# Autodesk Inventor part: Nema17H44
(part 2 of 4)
sketch "Эскиз49"
  geometry: L1 (-4, 0)-(-4, 283.577) reference; L2 (0, 283.577)-(0, 0) reference; L3 (0, 0)-(-4, 0) reference; L4 (-4, 283.577)-(0, 283.577) reference; L5 (0, 0)-(60, 0); L6 (60, 0)-(60, 283.577); L7 (60, 283.577)-(0, 283.577); L8 (0, 283.577)-(0, 0); L9 (-4, 25)-(0, 25); L10 (0, 25)-(0, 55); L11 (0, 55)-(-4, 55); L12 (-4, 55)-(-4, 25); L13 (0, 122.859)-(-4, 122.859); L14 (0, 92.859)-(0, 122.859); L15 (-4, 122.859)-(-4, 92.859); L16 (-4, 92.859)-(0, 92.859); L17 (0, 190.718)-(-4, 190.718); L18 (0, 160.718)-(0, 190.718); L19 (-4, 190.718)-(-4, 160.718); L20 (-4, 160.718)-(0, 160.718); L21 (0, 258.577)-(-4, 258.577); L22 (0, 228.577)-(0, 258.577); L23 (-4, 258.577)-(-4, 228.577); L24 (-4, 228.577)-(0, 228.577); L25 (0, 260)-(0, 283.577) reference; L26 (26.106, 260.239)-(0, 260) reference; L27 (0, 283.577)-(26.106, 283.338) reference; C1 r 12 at (26, 24.788) reference; C2 r 4 at (26, 271.788) reference; C3 r 4 at (26, 24.788); C4 r 4 at (26, 271.788); C5 r 2.25 at (10.45, 40.338) reference; C6 r 2.25 at (41.55, 40.338) reference; C7 r 2.25 at (10.45, 9.238) reference; C8 r 2.25 at (41.55, 9.238) reference; C9 r 7.35 at (26, 271.788) reference; C10 r 1.5 at (10.45, 40.338) reference; C11 r 1.5 at (41.55, 40.338) reference; C12 r 1.5 at (41.55, 9.238) reference; C13 r 1.5 at (10.45, 9.238) reference; A1 r 11.55 centre (26, 271.788) between (26.106, 260.239) and (26.106, 283.338) reference; 17 further points
  constraints: 40 end point, 4 parallel, 2 centre point, 2 coincident, 2 horizontal, 2 perpendicular, 2 point on line, 1 vertical, 24 other
  dimensions: "d382" = 60 distance of L2.end L5.end; "d383" = 8 diameter of C3; "d384" = 8 diameter of C4; "d385" = 30 distance between parallel lines of L9 L11; "d386" = 25 distance between parallel lines of L3 L9; "d389" = 67.85896 distance of L10.end L13.start (derived); "d394" = 25 distance from line of L21 L1.end
extrude "Выдавливание34" new body sketch "Эскиз49" distance "d395" = 4; taper "d396" = 0 deg
sketch "Эскиз50"
  geometry: C1 r 1.5 at (-16, 247) reference; C2 r 2 at (-16, 247); 1 further point
  constraints: 1 centre point, 1 coincident
  dimensions: "d399" = 4 diameter of C2
extrude "Выдавливание35" cut sketch "Эскиз50" distance "d400" = 4; taper "d401" = 0 deg
sketch "Эскиз51"
  geometry: C1 r 2 at (-16, 247); C2 r 4 at (-16, 247); A1 r 2 centre (-16, 247) between (-15.929, 245.001) and (-15.929, 248.999) reference; 3 further points
  constraints: 2 centre point, 2 coincident
  dimensions: "d402" = 4 diameter of C1; "d403" = 8 diameter of C2
extrude "Выдавливание36" join sketch "Эскиз51" distance "d404" = 1.5; taper "d405" = 0 deg
fillet "Сопряжение23" dims "d406" = 1
chamfer "Фаска24" distance "d407" = 0.5; stored, may be unused: second distance "d408" = 8, angle "d409" = 45 deg
fillet "Сопряжение24" dims "d410" = 1
feature "Комбинировать1"
feature "Толщина1" dims "d411" = 0.1, "d412" = 0.1
feature "Толщина2" dims "d413" = 0.1, "d414" = 0.1
feature "Толщина3" dims "d415" = 0.1, "d416" = 0.1
feature "Толщина4" dims "d417" = 0.1, "d418" = 0.1
sketch "Эскиз56"
  geometry: L1 (17.172, 21)-(-17.172, 21); L2 (-22, 16.172)-(-22, -16.172); L3 (-21.414, -17.586)-(-18.586, -20.414); L4 (-17.172, -21)-(17.172, -21); L5 (22, -16.172)-(22, 16.172); L6 (21.414, 17.586)-(18.586, 20.414); L7 (18.586, -20.414)-(21.414, -17.586); L8 (-18.586, 20.414)-(-21.414, 17.586); C1 r 1.9 at (-15.25, -15.25); C2 r 12 at (0, 0); C3 r 1.9 at (15.25, -15.25); C4 r 1.9 at (-15.25, 15.25); C5 r 1.9 at (15.25, 15.25); C6 r 4 at (0, 0) reference; A1 r 2 centre (-20, -16.172) between (-22, -16.172) and (-21.414, -17.586); A2 r 2 centre (-17.172, -19) between (-18.586, -20.414) and (-17.172, -21); A3 r 2 centre (20, -16.172) between (21.414, -17.586) and (22, -16.172); A4 r 2 centre (17.172, -19) between (17.172, -21) and (18.586, -20.414); A5 r 2 centre (17.172, 19) between (18.586, 20.414) and (17.172, 21); A6 r 2 centre (20, 16.172) between (22, 16.172) and (21.414, 17.586); A7 r 2 centre (-17.172, 19) between (-17.172, 21) and (-18.586, 20.414); A8 r 2 centre (-20, 16.172) between (-21.414, 17.586) and (-22, 16.172); 4 further points
  constraints: 16 end point, 16 point on circle, 13 centre point, 2 midpoint, 1 horizontal alignment, 1 vertical alignment
extrude "Выдавливание41" new body sketch "Эскиз56" distance "d440" = 40; taper "d441" = 0 deg
sketch "Эскиз57"
  geometry: L1 (-42.586, 38.857)-(-45.414, 36.028); L2 (-46, 34.614)-(-46, 2.271); L3 (-6.828, 39.443)-(-41.172, 39.443); L4 (-45.414, 0.857)-(-42.586, -1.972); L5 (-2, 2.271)-(-2, 34.614); L6 (-41.172, -2.557)-(-6.828, -2.557); L7 (-5.414, -1.972)-(-2.586, 0.857); L8 (-2.586, 36.028)-(-5.414, 38.857); L9 (-42.586, 266.553)-(-45.414, 263.724); L10 (-46, 262.31)-(-46, 229.967); L11 (-6.828, 267.139)-(-41.172, 267.139); L12 (-45.414, 228.553)-(-42.586, 225.724); L13 (-2, 229.967)-(-2, 262.31); L14 (-41.172, 225.139)-(-6.828, 225.139); L15 (-5.414, 225.724)-(-2.586, 228.553); L16 (-2.586, 263.724)-(-5.414, 266.553); C1 r 1.9 at (-39.25, 33.693); C2 r 1.9 at (-39.25, 3.193); C3 r 1.9 at (-8.75, 33.693); C4 r 12 at (-24, 18.443); C5 r 1.9 at (-8.75, 3.193); C6 r 1.9 at (-39.25, 261.389); C7 r 1.9 at (-39.25, 230.889); C8 r 1.9 at (-8.75, 261.389); C9 r 12 at (-24, 246.139); C10 r 1.9 at (-8.75, 230.889); A1 r 2 centre (-44, 34.614) between (-45.414, 36.028) and (-46, 34.614); A2 r 2 centre (-41.172, 37.443) between (-41.172, 39.443) and (-42.586, 38.857); A3 r 2 centre (-44, 2.271) between (-46, 2.271) and (-45.414, 0.857); A4 r 2 centre (-41.172, -0.557) between (-42.586, -1.972) and (-41.172, -2.557); A5 r 2 centre (-6.828, -0.557) between (-6.828, -2.557) and (-5.414, -1.972); A6 r 2 centre (-4, 2.271) between (-2.586, 0.857) and (-2, 2.271); A7 r 2 centre (-6.828, 37.443) between (-5.414, 38.857) and (-6.828, 39.443); A8 r 2 centre (-4, 34.614) between (-2, 34.614) and (-2.586, 36.028); A9 r 2 centre (-44, 262.31) between (-45.414, 263.724) and (-46, 262.31); A10 r 2 centre (-41.172, 265.139) between (-41.172, 267.139) and (-42.586, 266.553); A11 r 2 centre (-44, 229.967) between (-46, 229.967) and (-45.414, 228.553); A12 r 2 centre (-41.172, 227.139) between (-42.586, 225.724) and (-41.172, 225.139); A13 r 2 centre (-6.828, 227.139) between (-6.828, 225.139) and (-5.414, 225.724); A14 r 2 centre (-4, 229.967) between (-2.586, 228.553) and (-2, 229.967); A15 r 2 centre (-6.828, 265.139) between (-5.414, 266.553) and (-6.828, 267.139); A16 r 2 centre (-4, 262.31) between (-2, 262.31) and (-2.586, 263.724); A17 r 13 centre (-24, 246.139) between (-20.15, 233.722) and (-27.85, 233.722) reference; A18 r 13 centre (-24, 18.443) between (-27.85, 30.859) and (-20.15, 30.859) reference; 3 further points
  constraints: 32 end point, 32 point on circle, 26 centre point
extrude "Выдавливание42" join sketch "Эскиз57" distance "d442" = 40; taper "d443" = 0 deg
sketch "Эскиз58"
  geometry: C1 r 3.65 at (15.55, -15.55) reference; C2 r 1.65 at (15.55, -15.55) reference; C3 r 1.65 at (-15.55, -15.55) reference; C4 r 2 at (-15.55, -15.55); C5 r 2 at (15.55, -15.55); C6 r 3.65 at (15.55, -212.146) reference; C7 r 3.65 at (-15.55, -212.146) reference; C8 r 2 at (15.55, -212.146); C9 r 2 at (-15.55, -212.146); 1 further point
  constraints: 4 centre point, 4 coincident, 3 equal radius
  dimensions: "d444" = 4 diameter of C4
extrude "Выдавливание43" cut sketch "Эскиз58" distance "d446" = 5; taper "d447" = 0 deg
chamfer "Фаска25" distance "d448" = 1; stored, may be unused: second distance "d449" = 2, angle "d450" = 45 deg
node "РабПлоскость9"
sketch "Эскиз73"
  geometry: L1 (321, 97.659)-(321, 122.613); L2 (325.8, 34.5)-(325.8, 41.5); L3 (321, 41.5)-(321, 34.5); L4 (322.5, 34.3)-(322.5, 29.5); L5 (322.5, 29.5)-(329, 29.5); L6 (329, 29.5)-(329, 46.5); L7 (329, 46.5)-(322.5, 46.5); L8 (322.5, 46.5)-(322.5, 41.7); L9 (322.5, 41.7)-(326, 41.7); L10 (326, 41.7)-(326, 34.3); L11 (326, 34.3)-(322.5, 34.3); L12 (321, -2.5)-(321, 57.5) reference; L13 (332, 29.5)-(340, 29.5) reference; L14 (325.8, 38)-(323.934, 38); L15 (321, 34.5)-(324.333, 34.5); L16 (325.333, 34.5)-(325.8, 34.5); L17 (325.8, 41.5)-(325.333, 41.5); L18 (324.333, 41.5)-(321, 41.5); A1 r 0.5 centre (324.833, 34.5) between (325.333, 34.5) and (324.333, 34.5); A2 r 0.5 centre (324.833, 41.5) between (324.333, 41.5) and (325.333, 41.5); 2 further points
  constraints: 32 end point, 6 parallel, 5 horizontal, 4 perpendicular, 4 point on circle, 4 vertical, 3 symmetric about line, 2 centre point, 2 collinear, 2 equal length, 2 horizontal alignment, 2 midpoint, 1 point on line, 1 other
  dimensions: "d549" = 4.8 distance of L2.end L3.start; "d550" = 7 distance of L2.start L2.end; "d552" = 0.2 distance between parallel lines of L2 L10; "d553" = 6.5 distance of L4.end L5.end; "d554" = 1.5 distance between parallel lines of L1 L4; "d555" = 17 distance of L5.end L6.end; "d560" = 1.16667 distance from line of L10 A1.centre (derived); "d561" = 2.33333 distance from line of L4 A1.centre (derived); "d562" = 1 diameter of A1; "d563" = 4.8 distance between parallel lines of L3 L2; "d564" = 0.2 distance between parallel lines of L18 L9 (derived)
extrude "Выдавливание55" new body sketch "Эскиз73" stored distance "d556" = 22.5; taper "d558" = 0 deg; dims "d557" = 105, "d559" = 0
node "РабПлоскость12"
sketch "Эскиз74"
  geometry: L1 (325.8, -41.5)-(325.8, -34.5) reference; L2 (325.8, -34.5)-(325.333, -34.5) reference; L3 (324.333, -34.5)-(321, -34.5) reference; L4 (321, -34.5)-(321, -41.5) reference; L5 (321, -41.5)-(324.333, -41.5) reference; L6 (325.333, -41.5)-(325.8, -41.5) reference; A1 r 0.5 centre (324.833, -34.5) between (324.333, -34.5) and (325.333, -34.5) reference; A2 r 0.5 centre (324.833, -41.5) between (325.333, -41.5) and (324.333, -41.5) reference; 1 further point
extrude "Выдавливание56" new body sketch "Эскиз74" distance "d565" = 98; taper "d567" = 0 deg; dims "d566" = 122, "d568" = 0
sketch "Эскиз75"
  geometry: L1 (325.8, -41.5)-(325.8, -34.5) reference; L2 (325.8, -34.5)-(325.333, -34.5) reference; L3 (324.333, -34.5)-(321, -34.5) reference; L4 (321, -34.5)-(321, -41.5) reference; L5 (321, -41.5)-(324.333, -41.5) reference; L6 (325.333, -41.5)-(325.8, -41.5) reference; A1 r 0.5 centre (324.833, -34.5) between (324.333, -34.5) and (325.333, -34.5) reference; A2 r 0.5 centre (324.833, -41.5) between (325.333, -41.5) and (324.333, -41.5) reference; 1 further point
extrude "Выдавливание57" cut sketch "Эскиз75" distance "d569" = 95; taper "d570" = 0 deg
sketch "Эскиз76"
  geometry: L1 (6, -0.013)-(6.55, 246.985); L2 (8, 247)-(8, 0); L3 (0, 0)-(0, 247); L4 (-6, -0.013)-(-6.55, 246.985); L5 (-8, 247)-(-8, 0); C1 r 3 at (0, 0) reference; C2 r 3 at (0, 247) reference; A1 r 6.55 centre (0, 247) between (6.55, 246.985) and (-6.55, 246.985); A2 r 8 centre (0, 247) between (8, 247) and (-8, 247); A3 r 6 centre (0, 0) between (-6, -0.013) and (6, -0.013); A4 r 8 centre (0, 0) between (-8, 0) and (8, 0); 8 further points
  constraints: 10 end point, 8 point on circle, 8 tangent, 4 centre point, 4 symmetric about line, 3 vertical, 1 horizontal alignment, 9 other
extrude "Выдавливание58" new body sketch "Эскиз76" distance "d572" = 6; taper "d573" = 0 deg
sketch "Эскиз78"
  geometry: L1 (-14.5, 7.25)-(-2.5, 7.25); L2 (-2.5, 7.25)-(-2.5, 15.25); L3 (-2.5, 15.25)-(-14.5, 15.25); L4 (-14.5, 15.25)-(-14.5, 7.25); L5 (0, 0)-(0, 22.5) reference; L6 (-17, 22.5)-(0, 22.5) reference; L7 (-17, 0)-(-17, 22.5) reference; L8 (0, 0)-(-17, 0) reference; C1 r 1 at (-14.5, 7.25); C2 r 1 at (-14.5, 15.25); C3 r 1 at (-2.5, 7.25); C4 r 1 at (-2.5, 15.25); 8 further points
  constraints: 8 end point, 4 centre point, 4 coincident, 4 midpoint, 2 horizontal, 2 parallel, 1 horizontal alignment, 1 perpendicular, 1 vertical, 1 vertical alignment, 9 other
  dimensions: "d575" = 12 distance of L3.end L2.end; "d576" = 8 distance of L2.end L1.end; "d579" = 8 distance of L1.start point (-14.5, 15.25) (derived); "d582" = 12 distance of L1.start point (-2.5, 7.25) (derived); "d585" = 2 diameter of C1
extrude "Выдавливание59" cut sketch "Эскиз78" distance "d586" = 5; taper "d587" = 0 deg
sketch "Эскиз79"
  geometry: L1 (0, 0)-(0, 22.5) reference; L2 (-17, 22.5)-(0, 22.5) reference; L3 (-17, 0)-(-17, 22.5) reference; L4 (0, 0)-(-17, 0) reference; C1 r 1 at (-14.5, 15.25) reference; C2 r 1 at (-14.5, 7.25) reference; C3 r 1 at (-2.5, 15.25) reference; C4 r 1 at (-2.5, 7.25) reference; 1 further point
extrude "Выдавливание60" new body sketch "Эскиз79" distance "d588" = 3; taper "d589" = 0 deg
sketch "Эскиз80"
  geometry: L1 (-17, 22.5)-(-17, 0) reference; L2 (-17, 20.25)-(63, 20.25); L3 (63, 20.25)-(63, 2.25); L4 (63, 2.25)-(-17, 2.25); L5 (-17, 2.25)-(-17, 20.25); C1 r 1 at (-2.5, 15.25) reference; C2 r 1 at (-2.5, 7.25) reference; C3 r 1 at (-14.5, 15.25) reference; C4 r 1 at (-14.5, 7.25) reference; 4 further points
  constraints: 8 end point, 2 midpoint, 2 parallel, 1 horizontal, 1 horizontal alignment, 1 perpendicular, 1 point on line
  dimensions: "d590" = 18 distance of L2.end L3.end; "d643" = 80 distance of L2.start L2.end
extrude "Выдавливание61" join sketch "Эскиз80" distance "d591" = 3; taper "d592" = 0 deg
sketch "Эскиз81"
  geometry: L1 (-17, 22.5)-(-17, 0) reference; L2 (-17, 0)-(0, 0) reference; L3 (0, 0)-(0, 2.25) reference; L4 (0, 2.25)-(63, 2.25) reference; L5 (63, 2.25)-(63, 20.25) reference; L6 (63, 20.25)-(0, 20.25) reference; L7 (0, 20.25)-(0, 22.5) reference; L8 (0, 22.5)-(-17, 22.5) reference; L9 (0, 22.5)-(3, 22.5); L10 (3, 22.5)-(3, 0); L11 (3, 0)-(0, 0); L12 (0, 0)-(0, 22.5); 9 further points
  constraints: 8 end point, 2 parallel, 1 collinear, 1 horizontal, 1 perpendicular
  dimensions: "d593" = 3 distance between parallel lines of L12 L10
extrude "Выдавливание62" join sketch "Эскиз81" distance "d594" = 9.5; taper "d595" = 0 deg
sketch "Эскиз82"
  geometry: L1 (0, 0)-(0, 18); L2 (0, 0)-(3, 0); L3 (3, 18)-(3, 0); L4 (0, 0)-(3, 0) reference; L5 (5, 0)-(5, 18); L6 (0, 18)-(0, 0); L7 (5, 18)-(3.65, 18); L8 (1.35, 18)-(0, 18); L9 (0, 0)-(1.35, 0); L10 (3.65, 0)-(5, 0); A1 r 1.15 centre (2.5, 0) between (3.65, 0) and (1.35, 0); A2 r 1.15 centre (2.5, 18) between (1.35, 18) and (3.65, 18); 2 further points
  constraints: 12 end point, 5 parallel, 4 point on circle, 2 centre point, 2 collinear, 2 equal length, 2 horizontal, 2 perpendicular, 1 equal radius, 1 horizontal alignment, 1 point on line, 1 vertical alignment
  dimensions: "d599" = 5 distance of L6.start L5.end; "d600" = 2.3 diameter of A2 (derived)
extrude "Выдавливание63" join sketch "Эскиз82" stored distance "d601" = 46.75; taper "d602" = 0 deg
sketch "Эскиз83"
  geometry: L1 (3, 18)-(3, 16.964) reference; L2 (0, 18)-(3, 18) reference; L3 (0, 0)-(0, 18) reference; L4 (0, 0)-(3, 0) reference; L5 (3, 1.036)-(3, 0) reference; L6 (3.65, 0)-(5, 0) reference; L7 (5, 0)-(5, 18) reference; L8 (5, 18)-(3.65, 18) reference; A1 r 1.15 centre (2.5, 0) between (3.65, 0) and (3, 1.036) reference; A2 r 1.15 centre (2.5, 18) between (3, 16.964) and (3.65, 18) reference; 5 further points
  constraints: 2 coincident, 6 other
extrude "Выдавливание64" cut sketch "Эскиз83" stored distance "d603" = 10; taper "d604" = 0 deg
sketch "Эскиз84"
  geometry: L1 (3.65, 0)-(5, 0) reference; L2 (5, 0)-(5, 18) reference; L3 (5, 18)-(3.65, 18) reference; L4 (0, 18)-(1.35, 18) reference; L5 (0, 0)-(0, 18) reference; L6 (0, 0)-(1.35, 0) reference; L7 (2.5, 5)-(2.5, 13); C1 r 0.85 at (2.5, 5); C2 r 0.85 at (2.5, 13); A1 r 1.15 centre (2.5, 0) between (3.65, 0) and (1.35, 0) reference; A2 r 1.15 centre (2.5, 18) between (1.35, 18) and (3.65, 18) reference; 3 further points
  constraints: 2 centre point, 2 end point, 2 midpoint, 1 equal radius, 1 horizontal alignment, 1 point on line, 1 vertical
  dimensions: "d605" = 8 distance of L7.start L7.end; "d606" = 1.7 diameter of C2
extrude "Выдавливание65" cut sketch "Эскиз84" distance "d607" = 15; taper "d608" = 0 deg
chamfer "Фаска29" distance "d609" = 0.5; stored, may be unused: second distance "d610" = 5, angle "d611" = 45 deg
node "РабПлоскость10"
sketch "Эскиз86"
  geometry: L1 (1.35, -0.3)-(3.65, -0.3); L2 (3.65, -0.3)-(5, -0.3); L3 (5, -0.3)-(5, -3.45); L4 (5, -3.45)-(-4.4, -3.45); L5 (-4.4, -3.45)-(-4.4, 9); L6 (-6.003, 9)-(10.43, 9); L7 (0, 0)-(0, 18) reference; L8 (5, 0)-(5, 18) reference; L9 (1.35, -0.3)-(-0.4, -0.3); L10 (-0.4, -0.3)-(-0.4, 9); L11 (1.35, 18.3)-(3.65, 18.3); L12 (1.35, 18.3)-(-0.4, 18.3); L13 (3.65, 18.3)-(5, 18.3); L14 (5, 18.3)-(5, 21.45); L15 (5, 21.45)-(-4.4, 21.45); L16 (5, 18)-(5, 12.212); L17 (-4.4, 21.45)-(-4.4, 9); L18 (-0.4, 18.3)-(-0.4, 9); C1 r 1 at (2.5, 0); C2 r 1 at (2.5, 18); C3 r 1 at (2.5, 18); A1 r 1.15 centre (2.5, 0) between (3.65, 0) and (1.35, 0) reference; A2 r 1.15 centre (2.5, 18) between (1.35, 18) and (3.65, 18) reference; A3 r 1.15 centre (2.5, -0.3) between (1.35, -0.3) and (3.65, -0.3); A4 r 1.15 centre (2.5, 18.3) between (3.65, 18.3) and (1.35, 18.3); A5 r 1.15 centre (2.5, 18) between (1.35, 18) and (3.65, 18); 3 further points
  constraints: 32 end point, 11 symmetric about line, 6 centre point, 6 point on circle, 4 horizontal, 3 coincident, 3 midpoint, 3 point on line, 2 vertical, 1 collinear, 1 equal radius, 1 parallel, 1 perpendicular, 1 vertical alignment, 3 other
  dimensions: "d615" = 2 diameter of C1 (derived); "d616" = 2 diameter of C2 (derived); "d617" = 0.3 distance of A3.centre A1.centre; "d618" = 2 distance edge to line of A3 L4; "d620" = 0.4 distance between parallel lines of L7 L10; "d621" = 4 distance between parallel lines of L10 L5
extrude "Выдавливание67" new body sketch "Эскиз86" distance "d622" = 35; taper "d623" = 0 deg
sketch "Эскиз87"
  geometry: L1 (5, -3.45)-(5, -0.3) reference; L2 (5, -0.3)-(3.65, -0.3) reference; L3 (1.35, -0.3)-(-0.4, -0.3) reference; L4 (-0.4, -0.3)-(-0.4, 18.3) reference; L5 (-0.4, 18.3)-(1.35, 18.3) reference; L6 (3.65, 18.3)-(5, 18.3) reference; L7 (5, 18.3)-(5, 21.45) reference; L8 (5, 21.45)-(-4.4, 21.45) reference; L9 (-4.4, 21.45)-(-4.4, -3.45) reference; L10 (-4.4, -3.45)-(5, -3.45) reference; L11 (3.65, 18.3)-(1.35, 18.3); L12 (3.65, -0.3)-(1.35, -0.3); A1 r 1.15 centre (2.5, -0.3) between (1.35, -0.3) and (3.65, -0.3) reference; A2 r 1.15 centre (2.5, 18.3) between (3.65, 18.3) and (1.35, 18.3) reference; 1 further point
  constraints: 4 end point, 1 horizontal, 1 parallel
extrude "Выдавливание68" join sketch "Эскиз87" distance "d624" = 1; taper "d625" = 0 deg
sketch "Эскиз88"
  geometry: L1 (-5, -0.3)-(-5, -3.45) reference; L2 (-5, -3.45)-(4.4, -3.45) reference; L3 (4.4, -3.45)-(4.4, 21.45) reference; L4 (4.4, 21.45)-(-5, 21.45) reference; L5 (-5, 21.45)-(-5, 18.3) reference; L6 (-5, 18.3)-(-3.65, 18.3) reference; L7 (-1.35, 18.3)-(0.4, 18.3) reference; L8 (0.4, 18.3)-(0.4, -0.3) reference; L9 (0.4, -0.3)-(-1.35, -0.3) reference; L10 (-3.65, -0.3)-(-5, -0.3) reference; L11 (-3.65, -0.3)-(-1.35, -0.3); L12 (-3.65, 18.3)-(-1.35, 18.3); L13 (-3.65, -0.3)-(-1.35, -0.3); A1 r 1.15 centre (-2.5, 18.3) between (-1.35, 18.3) and (-3.65, 18.3) reference; A2 r 1.15 centre (-2.5, -0.3) between (-3.65, -0.3) and (-1.35, -0.3) reference; 1 further point
  constraints: 6 end point, 3 horizontal, 1 point on circle
extrude "Выдавливание69" join sketch "Эскиз88" distance "d626" = 1; taper "d627" = 0 deg
fillet "Сопряжение27" dims "d628" = 1.4
fillet "Сопряжение28" dims "d629" = 1.15 (derived)
fillet "Сопряжение29" dims "d630" = 2
sketch "Эскиз89"
  geometry: L1 (-4.4, -3.45)-(5, -3.45); L2 (5, -3.45)-(5, 21.45); L3 (5, 21.45)-(-4.4, 21.45); L4 (-4.4, 21.45)-(-4.4, -3.45); L5 (-4.4, 20.05)-(-4.4, -2.05) reference; L6 (3.6, 21.45)-(-3, 21.45) reference; L7 (5, 0)-(5, 18) reference; L8 (-3, -3.45)-(3.6, -3.45) reference; C1 r 0.85 at (2.5, 5) reference; C2 r 0.85 at (2.5, 13) reference; A1 r 1.4 centre (-3, -2.05) between (-4.4, -2.05) and (-3, -3.45) reference; A2 r 1.4 centre (3.6, -2.05) between (3.6, -3.45) and (5, -2.05) reference; A3 r 1.4 centre (3.6, 20.05) between (5, 20.05) and (3.6, 21.45) reference; A4 r 1.4 centre (-3, 20.05) between (-3, 21.45) and (-4.4, 20.05) reference; 9 further points
  constraints: 8 end point, 4 collinear, 2 parallel, 1 horizontal, 1 perpendicular
extrude "Выдавливание70" new body sketch "Эскиз89" distance "d634" = 1.5; taper "d635" = 0 deg
chamfer "Фаска31" distance "d636" = 1.5; stored, may be unused: second distance "d637" = 5, angle "d638" = 45 deg
fillet "Сопряжение30" dims "d639" = 1
node "РабПлоскость11"
sketch "Эскиз93"
  geometry: L1 (30.25, -7)-(7.25, -7); L2 (7.25, -7)-(7.25, 17); L3 (7.25, 17)-(30.25, 17); L4 (30.25, 17)-(30.25, -7); L5 (30.25, 17)-(18.869, 17); L6 (18.869, 17)-(18.869, 22); L7 (18.869, 22)-(30.25, 22); L8 (30.25, 22)-(30.25, 17); L9 (30.25, 10)-(35, 10); L10 (35, 10)-(35, 12); L11 (35, 12)-(30.25, 12); L12 (30.25, 12)-(30.25, 10); L13 (7.25, 10)-(2.5, 10); L14 (2.5, 10)-(2.5, 12); L15 (2.5, 12)-(7.25, 12); L16 (7.25, 12)-(7.25, 10); L17 (26.4, 22)-(21.6, 22); L18 (21.6, 22)-(21.6, 25); L19 (21.6, 25)-(26.4, 25); L20 (26.4, 25)-(26.4, 22); L21 (24, 25)-(24, -7); L22 (-1.5, 11.191)-(-1.5, 6.809) reference; L23 (35, 0.1)-(30.65, 0.1); L24 (30.65, 0.1)-(30.65, 10); L25 (30.65, 10)-(35, 10); L26 (35, 10)-(35, 0.1); L27 (6.85, 0.1)-(2.5, 0.1); L28 (2.5, 0.1)-(2.5, 10); L29 (2.5, 10)-(6.85, 10); L30 (6.85, 10)-(6.85, 0.1); L31 (35, -0.3)-(35, -2.05) reference; C1 r 6.25 at (24, 13.089); 3 further points
  constraints: 58 end point, 14 parallel, 9 point on line, 8 perpendicular, 7 horizontal, 6 collinear, 3 midpoint, 1 centre point, 1 horizontal alignment, 1 tangent, 1 vertical alignment
  dimensions: "d647" = 24 distance of L1.end L2.end; "d648" = 23 distance of L2.end L3.end; "d649" = 32.5 distance between parallel lines of L14 L10; "d650" = 2 distance of L9.end L10.end; "d651" = 17 distance between parallel lines of L13 L1; "d652" = 32 distance between parallel lines of L1 L19; "d653" = 3 distance of L17.end L18.end; "d654" = 12.5 diameter of C1; "d655" = 4.8 distance between parallel lines of L20 L18; "d657" = 0.4 distance between parallel lines of L30 L2 (derived); "d658" = 0.4 distance between parallel lines of L4 L24; "d659" = 9.9 distance of L27.end L28.end
extrude "Выдавливание71" join sketch "Эскиз93" distance "d660" = 9; taper "d661" = 0 deg
fillet "Сопряжение31" dims "d662" = 4
fillet "Сопряжение32" dims "d663" = 1
sketch "Эскиз94"
  geometry: L1 (1.75, -1.175)-(1.75, 26.975); L2 (-1, 0)-(-1, -2.35) reference; L3 (-1, 28.15)-(-1, 25.8) reference; L4 (8, 31.65)-(8, -3.35) reference; C1 r 0.875 at (1.75, -1.175); C2 r 0.875 at (1.75, 26.975); 3 further points
  constraints: 2 centre point, 2 end point, 2 horizontal alignment, 2 midpoint, 1 equal radius, 1 vertical
  dimensions: "d664" = 1.75 diameter of C2; "d665" = 6.25 distance from line of L1.end L4
extrude "Выдавливание72" cut sketch "Эскиз94" distance "d666" = 15; taper "d667" = 0 deg
sketch "Эскиз95"
  geometry: L1 (-4.5, -24.4)-(8, -24.4); L2 (8, -24.4)-(8, -1.4); L3 (8, -1.4)-(-4.5, -1.4); L4 (-4.5, -1.4)-(-4.5, -24.4); L5 (8, 5.85)-(8, -29.15) reference; L6 (0, -1)-(8, -1) reference; L7 (8, -24.8)-(0, -24.8) reference; 1 further point
  constraints: 8 end point, 2 parallel, 1 collinear, 1 horizontal, 1 perpendicular
  dimensions: "d668" = 12.5 distance of L2.end L3.end; "d669" = 23 distance of L3.end L1.start; "d670" = 0.4 distance between parallel lines of L6 L3 (derived); "d671" = 0.4 distance between parallel lines of L7 L1 (derived)
extrude "Выдавливание73" new body sketch "Эскиз95" distance "d672" = 7; taper "d674" = 0 deg; dims "d673" = 17, "d675" = 0
sketch "Эскиз96"
  geometry: L1 (8, 24.4)-(-4.5, 24.4) reference; L2 (-4.5, 1.4)-(8, 1.4) reference; L3 (8, 0)-(8, -4.672) reference; L4 (-4.5, 1.4)-(8, 1.4); L5 (8, 1.4)-(8, -3.35); L6 (8, -3.35)-(-4.5, -3.35); L7 (-4.5, -3.35)-(-4.5, 1.4); L8 (-4.5, 24.4)-(8, 24.4); L9 (8, 24.4)-(8, 29.15); L10 (8, 29.15)-(-4.5, 29.15); L11 (-4.5, 29.15)-(-4.5, 24.4); L12 (4.292, 29.15)-(0, 29.15) reference; L13 (0, -3.35)-(4, -3.35) reference; C1 r 0.875 at (1.75, -1.175) reference; C2 r 0.875 at (1.75, 26.975) reference; 4 further points
  constraints: 16 end point, 4 parallel, 2 collinear, 2 horizontal, 2 perpendicular, 2 point on line
extrude "Выдавливание74" join sketch "Эскиз96" distance "d676" = 2; taper "d677" = 0 deg
sketch "Эскиз97"
  geometry: L1 (-4.5, -24.4)-(8, -24.4) reference; L2 (8, -24.4)-(8, -1.4) reference; L3 (8, -1.4)-(-4.5, -1.4) reference; L4 (-4.5, -1.4)-(-4.5, -24.4) reference; L5 (8, 5.85)-(8, -29.15) reference; A1 r 6.25 centre (1.75, -18.15) between (-1.241, -12.662) and (4.741, -12.662); A2 r 3 centre (1.75, -12.9) between (4.741, -12.662) and (-1.241, -12.662); 1 further point
  constraints: 4 point on circle, 3 tangent, 2 centre point, 1 vertical alignment
  dimensions: "d678" = 14.5 dimension on A2 L1; "d679" = 6 diameter of A2
extrude "Выдавливание75" join sketch "Эскиз97" distance "d680" = 5; taper "d681" = 0 deg
sketch "Эскиз98"
  geometry: C1 r 2.4 at (1.75, -18.15); A1 r 6.25 centre (1.75, -18.15) between (-1.241, -12.662) and (4.741, -12.662) reference; 1 further point
  constraints: 1 centre point, 1 coincident
  dimensions: "d682" = 4.8 diameter of C1
extrude "Выдавливание76" join sketch "Эскиз98" distance "d683" = 4; taper "d684" = 0 deg
sketch "Эскиз99"
  geometry: L1 (8.868, -3.544)-(6.055, -3.048); L2 (6.055, -3.048)-(6.055, -2.077); L3 (6.055, -2.077)-(8.868, -1.581); L4 (6.055, 0.877)-(6.055, 1.848); L5 (8.868, 0.381)-(6.055, 0.877); L6 (6.055, 1.848)-(8.868, 2.344); L7 (6.055, 4.802)-(6.055, 5.773); L8 (8.868, 4.306)-(6.055, 4.802); L9 (6.055, 5.773)-(8.868, 6.269); L10 (6.055, 8.727)-(6.055, 9.698); L11 (8.868, 8.231)-(6.055, 8.727); L12 (6.055, 9.698)-(8.868, 10.194); L13 (6.055, 12.652)-(6.055, 13.623); L14 (8.868, 12.156)-(6.055, 12.652); L15 (6.055, 13.623)-(8.868, 14.119); L16 (6.055, 16.577)-(6.055, 17.548); L17 (8.868, 16.081)-(6.055, 16.577); L18 (6.055, 17.548)-(8.868, 18.044); L19 (6.055, 20.502)-(6.055, 21.473); L20 (8.868, 20.006)-(6.055, 20.502); L21 (6.055, 21.473)-(8.868, 21.969); L22 (8.868, -7.469)-(6.055, -6.973); L23 (6.055, -6.973)-(6.055, -6.002); L24 (6.055, -6.002)-(8.868, -5.506); L25 (8.868, -11.394)-(6.055, -10.898); L26 (6.055, -10.898)-(6.055, -9.927); L27 (6.055, -9.927)-(8.868, -9.431); L28 (6.055, 24.427)-(6.055, 25.398); L29 (8.868, 23.931)-(6.055, 24.427); L30 (6.055, 25.398)-(8.868, 25.894); L31 (14.25, -11)-(7.65, -11) reference; L32 (14.25, 25.5)-(7.65, 25.5) reference; L33 (7.65, -11)-(6.25, -11) reference; L34 (7.25, 25.5)-(7.65, 25.5) reference; L35 (10.868, 25.894)-(10.868, -11); C1 r 7.5 at (-0.195, -0.271); C2 r 2.4 at (0, 0) reference; A1 r 4.594 centre (5.309, -4.945) between (8.571, -1.709) and (5.925, -0.392); A2 r 7.718 centre (3.905, 7.841) between (5.925, 0.392) and (8.583, 1.702); A3 r 5.938 centre (0, 0) between (5.925, -0.392) and (5.925, 0.392); A4 r 7.718 centre (7.274, 4.838) between (5.324, -2.629) and (8.274, -2.815); A5 r 7.718 centre (7.274, 4.838) between (5.324, -2.629) and (8.274, -2.815); A6 r 8.75 centre (-0.01, 0.003) between (8.274, -2.815) and (8.571, -1.709); A7 r 8.75 centre (-0.01, 0.003) between (8.274, -2.815) and (8.571, -1.709); A8 r 4.594 centre (5.309, -4.945) between (8.571, -1.709) and (5.925, -0.392); A9 r 7.718 centre (3.905, 7.841) between (5.925, 0.392) and (8.583, 1.702); A10 r 5.937 centre (0, 0) between (5.925, -0.392) and (5.925, 0.392) reference; A11 r 8.75 centre (0, 0) between (2.817, 8.284) and (1.712, 8.581); A12 r 8.75 centre (0, 0) between (2.817, 8.284) and (1.712, 8.581); A13 r 7.718 centre (7.834, 3.882) between (1.712, 8.581) and (0.392, 5.925); A14 r 7.718 centre (7.834, 3.882) between (1.712, 8.581) and (0.392, 5.925); A15 r 5.937 centre (0, 0) between (3.302, 4.935) and (2.629, 5.324); A16 r 5.937 centre (0, 0) between (3.302, 4.935) and (2.629, 5.324); A17 r 7.718 centre (-4.835, 7.284) between (2.629, 5.324) and (2.817, 8.284); A18 r 7.718 centre (-4.835, 7.284) between (2.629, 5.324) and (2.817, 8.284); A19 r 8.75 centre (0, 0) between (-2.817, -8.284) and (-1.712, -8.581); A20 r 8.75 centre (0, 0) between (1.702, -8.583) and (2.808, -8.287); A21 r 8.75 centre (0, 0) between (1.702, -8.583) and (2.808, -8.287); A22 r 7.718 centre (4.835, -7.284) between (-2.629, -5.324) and (-2.817, -8.284); A23 r 7.718 centre (4.835, -7.284) between (-2.629, -5.324) and (-2.817, -8.284); A24 r 7.718 centre (-7.834, -3.882) between (-1.712, -8.581) and (-0.392, -5.925); A25 r 7.718 centre (-7.834, -3.882) between (-1.712, -8.581) and (-0.392, -5.925); A26 r 5.937 centre (0, 0) between (-0.392, -5.925) and (0.385, -5.925); A27 r 5.937 centre (0, 0) between (-0.392, -5.925) and (0.385, -5.925); A28 r 7.718 centre (7.83, -3.891) between (0.385, -5.925) and (1.702, -8.583); A29 r 7.718 centre (7.83, -3.891) between (0.385, -5.925) and (1.702, -8.583); A30 r 7.718 centre (-4.844, -7.279) between (2.808, -8.287) and (2.623, -5.327); A31 r 7.718 centre (-4.844, -7.279) between (2.808, -8.287) and (2.623, -5.327); A32 r 8.75 centre (0, 0) between (-2.817, -8.284) and (-1.712, -8.581); A33 r 8.75 centre (0, 0) between (-6.582, -5.765) and (-5.773, -6.575); A34 r 5.938 centre (0, 0) between (-3.302, -4.935) and (-2.629, -5.324); A35 r 5.938 centre (0, 0) between (-3.302, -4.935) and (-2.629, -5.324); A36 r 7.718 centre (-8.726, 0.556) between (-5.773, -6.575) and (-3.302, -4.935); A37 r 7.718 centre (-8.726, 0.556) between (-5.773, -6.575) and (-3.302, -4.935); A38 r 7.718 centre (0.545, -8.726) between (-4.939, -3.296) and (-6.582, -5.765); A39 r 7.718 centre (0.545, -8.726) between (-4.939, -3.296) and (-6.582, -5.765); A40 r 8.75 centre (0, 0) between (-6.582, -5.765) and (-5.773, -6.575); A41 r 8.75 centre (0, 0) between (-8.583, -1.702) and (-8.287, -2.808); A42 r 5.937 centre (0, 0) between (-5.327, -2.623) and (-4.939, -3.296); A43 r 5.937 centre (0, 0) between (-5.327, -2.623) and (-4.939, -3.296); A44 r 7.718 centre (-7.279, 4.844) between (-8.287, -2.808) and (-5.327, -2.623); A45 r 7.718 centre (-7.279, 4.844) between (-8.287, -2.808) and (-5.327, -2.623); A46 r 5.937 centre (0, 0) between (-5.925, 0.392) and (-5.925, -0.385); A47 r 5.937 centre (0, 0) between (-5.925, 0.392) and (-5.925, -0.385); A48 r 8.75 centre (0, 0) between (-8.583, -1.702) and (-8.287, -2.808); A49 r 7.718 centre (-3.891, -7.83) between (-5.925, -0.385) and (-8.583, -1.702); A50 r 7.718 centre (-3.882, 7.834) between (-8.581, 1.712) and (-5.925, 0.392); A51 r 7.718 centre (-3.882, 7.834) between (-8.581, 1.712) and (-5.925, 0.392); A52 r 7.718 centre (-3.891, -7.83) between (-5.925, -0.385) and (-8.583, -1.702); A53 r 8.75 centre (0, 0) between (8.583, 1.702) and (8.287, 2.808); A54 r 8.75 centre (0, 0) between (6.582, 5.765) and (5.773, 6.575); A55 r 8.75 centre (0, 0) between (6.582, 5.765) and (5.773, 6.575); A56 r 8.75 centre (0, 0) between (8.583, 1.702) and (8.287, 2.808); A57 r 5.937 centre (0, 0) between (5.327, 2.623) and (4.939, 3.296); A58 r 5.937 centre (0, 0) between (5.327, 2.623) and (4.939, 3.296); A59 r 7.718 centre (8.726, -0.556) between (5.773, 6.575) and (3.302, 4.935); A60 r 7.718 centre (8.726, -0.556) between (5.773, 6.575) and (3.302, 4.935); A61 r 7.718 centre (-0.545, 8.726) between (4.939, 3.296) and (6.582, 5.765); A62 r 7.718 centre (-0.545, 8.726) between (4.939, 3.296) and (6.582, 5.765); A63 r 7.718 centre (7.279, -4.844) between (8.287, 2.808) and (5.327, 2.623); A64 r 7.718 centre (7.279, -4.844) between (8.287, 2.808) and (5.327, 2.623)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; 40 further points
  constraints: 193 point on circle, 97 centre point, 62 end point, 45 vertical alignment, 18 parallel, 9 collinear, 1 equal length, 1 midpoint, 1 perpendicular, 1 point on line, 1 vertical, 8 other
  dimensions: "d685" = 15 diameter of C1; "d687" = 9.0625 dimension on C1.centre; "d689" = 20 deg angle of L3 L1; "d690" = 2.8125 dimension on L2; "d691" = 1.96344 distance of L3.end L1.start; "d694" = 3.925 distance of L1.end L4.start; "d701" = 3.925 distance of L1.start L22.start; "d706" = 0.39422 distance from line of L31 L25.start (derived); "d707" = 0.39422 distance from line of L32 L30.end (derived); "d708" = 2 dimension on L35
extrude "Выдавливание77" new body sketch "Эскиз99" distance "d709" = 3.5; taper "d710" = 0 deg
sketch "Эскиз100"
  geometry: C1 r 2.4 at (0, 0) reference; A1 r 7.718 centre (-6.559, 5.781) between (1.158, 5.823) and (0.572, 8.731); A2 r 7.718 centre (-6.559, 5.781) between (1.158, 5.823) and (0.572, 8.731); A3 r 8.75 centre (0, 0) between (0.572, 8.731) and (-0.572, 8.731); A4 r 8.75 centre (0, 0) between (0.572, 8.731) and (-0.572, 8.731); A5 r 7.718 centre (6.559, 5.781) between (-0.572, 8.731) and (-1.158, 5.823); A6 r 7.718 centre (6.559, 5.781) between (-0.572, 8.731) and (-1.158, 5.823); A7 r 5.937 centre (0, 0) between (-1.158, 5.823) and (-1.909, 5.622); A8 r 5.937 centre (0, 0) between (-1.158, 5.823) and (-1.909, 5.622); A9 r 8.75 centre (0, 0) between (-3.87, 7.848) and (-4.861, 7.275); A10 r 7.718 centre (-8.571, 1.727) between (-1.909, 5.622) and (-3.87, 7.848); A11 r 8.75 centre (0, 0) between (-7.275, 4.861) and (-7.848, 3.87); A12 r 8.75 centre (0, 0) between (-7.275, 4.861) and (-7.848, 3.87); A13 r 7.718 centre (-8.286, -2.79) between (-4.464, 3.915) and (-7.275, 4.861); A14 r 7.718 centre (-8.286, -2.79) between (-4.464, 3.915) and (-7.275, 4.861); A15 r 5.937 centre (0, 0) between (-3.915, 4.464) and (-4.464, 3.915); A16 r 5.937 centre (0, 0) between (-3.915, 4.464) and (-4.464, 3.915); A17 r 7.718 centre (2.79, 8.286) between (-4.861, 7.275) and (-3.915, 4.464); A18 r 7.718 centre (2.79, 8.286) between (-4.861, 7.275) and (-3.915, 4.464); A19 r 8.75 centre (0, 0) between (-3.87, 7.848) and (-4.861, 7.275); A20 r 7.718 centre (-8.571, 1.727) between (-1.909, 5.622) and (-3.87, 7.848); A21 r 8.75 centre (0, 0) between (7.275, -4.861) and (7.848, -3.87); A22 r 8.75 centre (0, 0) between (3.87, -7.848) and (4.861, -7.275); A23 r 5.937 centre (0, 0) between (1.158, -5.823) and (1.909, -5.622); A24 r 5.937 centre (0, 0) between (1.158, -5.823) and (1.909, -5.622); A25 r 5.937 centre (0, 0) between (3.915, -4.464) and (4.464, -3.915); A26 r 5.937 centre (0, 0) between (3.915, -4.464) and (4.464, -3.915); A27 r 7.718 centre (1.727, -8.571) between (7.848, -3.87) and (5.622, -1.909); A28 r 7.718 centre (1.727, -8.571) between (7.848, -3.87) and (5.622, -1.909); A29 r 7.718 centre (8.286, 2.79) between (4.464, -3.915) and (7.275, -4.861); A30 r 7.718 centre (8.286, 2.79) between (4.464, -3.915) and (7.275, -4.861); A31 r 8.75 centre (0, 0) between (7.275, -4.861) and (7.848, -3.87); A32 r 7.718 centre (-2.79, -8.286) between (4.861, -7.275) and (3.915, -4.464); A33 r 7.718 centre (-2.79, -8.286) between (4.861, -7.275) and (3.915, -4.464); A34 r 7.718 centre (8.571, -1.727) between (1.909, -5.622) and (3.87, -7.848); A35 r 8.75 centre (0, 0) between (3.87, -7.848) and (4.861, -7.275); A36 r 7.718 centre (8.571, -1.727) between (1.909, -5.622) and (3.87, -7.848); A37 r 8.75 centre (0, 0) between (8.731, -0.572) and (8.731, 0.572); A38 r 8.75 centre (0, 0) between (7.848, 3.87) and (7.275, 4.861); A39 r 8.75 centre (0, 0) between (7.848, 3.87) and (7.275, 4.861); A40 r 7.718 centre (8.286, -2.79) between (7.275, 4.861) and (4.464, 3.915); A41 r 7.718 centre (8.286, -2.79) between (7.275, 4.861) and (4.464, 3.915); A42 r 7.718 centre (1.727, 8.571) between (5.622, 1.909) and (7.848, 3.87); A43 r 7.718 centre (1.727, 8.571) between (5.622, 1.909) and (7.848, 3.87); A44 r 7.718 centre (5.781, -6.559) between (8.731, 0.572) and (5.823, 1.158); A45 r 7.718 centre (5.781, -6.559) between (8.731, 0.572) and (5.823, 1.158); A46 r 5.937 centre (0, 0) between (5.823, 1.158) and (5.622, 1.909); A47 r 7.718 centre (5.781, 6.559) between (5.823, -1.158) and (8.731, -0.572); A48 r 7.718 centre (5.781, 6.559) between (5.823, -1.158) and (8.731, -0.572); A49 r 5.937 centre (0, 0) between (5.823, 1.158) and (5.622, 1.909); A50 r 5.938 centre (0, 0) between (5.622, -1.909) and (5.823, -1.158); A51 r 5.938 centre (0, 0) between (5.622, -1.909) and (5.823, -1.158); A52 r 8.75 centre (0, 0) between (8.731, -0.572) and (8.731, 0.572); A53 r 8.75 centre (0, 0) between (-8.731, 0.572) and (-8.731, -0.572); A54 r 8.75 centre (0, 0) between (-8.731, 0.572) and (-8.731, -0.572); A55 r 8.75 centre (0, 0) between (-7.848, -3.87) and (-7.275, -4.861); A56 r 8.75 centre (0, 0) between (-7.848, -3.87) and (-7.275, -4.861); A57 r 5.937 centre (0, 0) between (-4.464, -3.915) and (-3.915, -4.464); A58 r 5.937 centre (0, 0) between (-4.464, -3.915) and (-3.915, -4.464); A59 r 5.937 centre (0, 0) between (-5.823, -1.158) and (-5.622, -1.909); A60 r 5.937 centre (0, 0) between (-5.823, -1.158) and (-5.622, -1.909); A61 r 7.718 centre (-8.286, 2.79) between (-7.275, -4.861) and (-4.464, -3.915); A62 r 7.718 centre (-8.286, 2.79) between (-7.275, -4.861) and (-4.464, -3.915); A63 r 7.718 centre (-1.727, -8.571) between (-5.622, -1.909) and (-7.848, -3.87); A64 r 7.718 centre (-1.727, -8.571) between (-5.622, -1.909) and (-7.848, -3.87)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; 1 further point
  constraints: 192 point on circle, 96 centre point
extrude "Выдавливание78" new body sketch "Эскиз100" distance "d711" = 3.5; taper "d712" = 0 deg
feature "Комбинировать9"
sketch "Эскиз101"
  geometry: L1 (0, 0)-(36.5, 0) reference; L2 (0, 0)-(36.5, 0) reference; L3 (0, 0)-(0, -3.5) reference; L4 (36.5, -3.5)-(0, -3.5) reference; L5 (36.5, 0)-(36.5, -3.5) reference; 3 further points
extrude "Выдавливание79" join sketch "Эскиз101" distance "d713" = 7.6; taper "d714" = 0 deg
sketch "Эскиз102"
  geometry: L1 (-29.5, 17.05)-(-5.5, 17.05); L2 (-5.5, 17.05)-(-5.5, 5.05); L3 (-5.5, 5.05)-(-29.5, 5.05); L4 (-29.5, 5.05)-(-29.5, 17.05); L5 (-35, 22.1)-(0, 22.1) reference; L6 (0, 22.1)-(0, 0) reference; C1 r 2 at (-29.5, 17.05); C2 r 2 at (-5.5, 17.05); C3 r 2 at (-29.5, 5.05); C4 r 2 at (-5.5, 5.05); 5 further points
  constraints: 8 end point, 4 centre point, 4 midpoint, 2 horizontal, 2 parallel, 1 horizontal alignment, 1 perpendicular, 1 vertical, 1 vertical alignment, 6 other
  dimensions: "d715" = 4 diameter of C1; "d716" = 24 distance of L1.start L1.end; "d717" = 12 distance of L3.end L1.start; "d720" = 24 distance of L1.start C2.centre (derived); "d723" = 12 distance of L1.start C3.centre (derived)
extrude "Выдавливание80" cut sketch "Эскиз102" distance "d726" = 5; taper "d727" = 0 deg
sketch "Эскиз103"
  geometry: C1 r 2 at (-29.5, 17.05) reference; C2 r 2 at (-29.5, 5.05) reference; C3 r 2 at (-5.5, 5.05) reference; C4 r 2 at (-5.5, 17.05) reference; C5 r 3.5 at (-29.5, 17.05); C6 r 3.5 at (-5.5, 17.05); C7 r 3.5 at (-5.5, 5.05); C8 r 3.5 at (-29.5, 5.05); 1 further point
  constraints: 4 centre point
  dimensions: "d728" = 1.5 radial gap between concentric circles of C1 C5; "d729" = 1.5 radial gap between concentric circles of C4 C6; "d730" = 1.5 radial gap between concentric circles of C3 C7; "d731" = 1.5 radial gap between concentric circles of C2 C8
extrude "Выдавливание81" join sketch "Эскиз103" distance "d732" = 1.5; taper "d733" = 0 deg
chamfer "Фаска33" distance "d734" = 0.75; stored, may be unused: second distance "d735" = 5, angle "d736" = 45 deg
sketch "Эскиз104"
  geometry: L1 (-35, 0)-(-35, 22.1) reference; L2 (-34.898, 28.05)-(-35, 28.05) reference; L3 (-35, 28.05)-(1.5, 28.05); L4 (1.5, 28.05)-(1.5, -1.4); L5 (1.5, -1.4)-(-35, -1.4); L6 (-35, -1.4)-(-35, 28.05); L7 (1.5, 0)-(1.5, 22.1) reference; L8 (-35, -1.4)-(0, -1.4) reference; C1 r 3.5 at (-29.5, 17.05) reference; C2 r 3.5 at (-5.5, 17.05) reference; C3 r 3.5 at (-5.5, 5.05) reference; C4 r 3.5 at (-29.5, 5.05) reference; C5 r 3.7 at (-5.5, 17.05); C6 r 3.7 at (-5.5, 5.05); C7 r 3.7 at (-29.5, 5.05); C8 r 3.7 at (-29.5, 17.05); 4 further points
  constraints: 8 end point, 4 centre point, 2 collinear, 2 parallel, 1 horizontal, 1 perpendicular
  dimensions: "d737" = 0.2 radial gap between concentric circles of C2 C5; "d738" = 0.2 radial gap between concentric circles of C3 C6; "d739" = 0.2 radial gap between concentric circles of C4 C7; "d740" = 0.2 radial gap between concentric circles of C1 C8
extrude "Выдавливание82" join sketch "Эскиз104" distance "d741" = 1.8; taper "d742" = 0 deg
sketch "Эскиз105"
  geometry: L1 (-35, 28.05)-(1.5, 28.05); L2 (1.5, 28.05)-(1.5, -1.4); L3 (1.5, -1.4)-(-35, -1.4); L4 (-35, -1.4)-(-35, 28.05); C1 r 2 at (-29.5, 17.05) reference; C2 r 2 at (-5.5, 17.05) reference; C3 r 2 at (-5.5, 5.05) reference; C4 r 2 at (-29.5, 5.05) reference; C5 r 1.5 at (-29.5, 17.05); C6 r 1.5 at (-5.5, 17.05); C7 r 1.5 at (-5.5, 5.05); C8 r 1.5 at (-29.5, 5.05); 2 further points
  constraints: 8 end point, 5 coincident, 4 centre point, 2 parallel, 1 horizontal, 1 perpendicular
  dimensions: "d743" = 3 diameter of C5; "d744" = 3 diameter of C6; "d745" = 3 diameter of C7; "d746" = 3 diameter of C8
extrude "Выдавливание83" join sketch "Эскиз105" distance "d747" = 2.2; taper "d748" = 0 deg
sketch "Эскиз108"
  geometry: L1 (-15, 0)-(1, 0) reference; L2 (3, 2)-(3, 2.25) reference; L3 (3, 2.25)-(63, 2.25) reference; L4 (63, 2.25)-(63, 20.25) reference; L5 (63, 20.25)-(3, 20.25) reference; L6 (3, 20.25)-(3, 20.5) reference; L7 (1, 22.5)-(-15, 22.5) reference; L8 (-17, 20.5)-(-17, 2) reference; L9 (-15, 22.5)-(-22, 22.5); L10 (-22, 22.5)-(-22, 0); L11 (-22, 0)-(-15, 0); L12 (-15, 0)-(-15, 22.5); L13 (3, 20.25)-(3, 2.25) reference; L14 (3, 20.25)-(3, 2.25); C1 r 1 at (-2.5, 15.25) reference; C2 r 1 at (-14.5, 15.25) reference; C3 r 1 at (-14.5, 7.25) reference; C4 r 1 at (-2.5, 7.25) reference; A1 r 2 centre (-15, 2) between (-17, 2) and (-15, 0) reference; A2 r 2 centre (1, 2) between (1, 0) and (3, 2) reference; A3 r 2 centre (1, 20.5) between (3, 20.5) and (1, 22.5) reference; A4 r 2 centre (-15, 20.5) between (-15, 22.5) and (-17, 20.5) reference; 2 further points
  constraints: 10 end point, 2 parallel, 1 collinear, 1 horizontal, 1 perpendicular, 1 vertical
  dimensions: "d750" = 5 distance between parallel lines of L8 L10
extrude "Выдавливание84" new body sketch "Эскиз108" distance "d751" = 3; taper "d752" = 0 deg
sketch "Эскиз110"
  geometry: L1 (-8, 247)-(-8, 0) reference; L2 (8, 0)-(8, 247) reference; L3 (6.55, 246.985)-(6, -0.013) reference; L4 (-6, -0.013)-(-6.55, 246.985) reference; L5 (-7.4, 0)-(-7.4, 247); L6 (7.4, 247)-(7.4, 0); A1 r 8 centre (0, 247) between (8, 247) and (-8, 247) reference; A2 r 8 centre (0, 0) between (-8, 0) and (8, 0) reference; A3 r 6 centre (0, 0) between (-6, -0.013) and (6, -0.013) reference; A4 r 6.55 centre (0, 247) between (6.55, 246.985) and (-6.55, 246.985) reference; A5 r 7.4 centre (0, 247) between (7.4, 247) and (-7.4, 247); A6 r 7.4 centre (0, 0) between (-7.4, 0) and (7.4, 0); 1 further point
  constraints: 4 end point, 4 point on circle, 2 centre point, 3 other
  dimensions: "d755" = 1.4 distance from line of L5 L4.start
extrude "Выдавливание85" cut sketch "Эскиз110" distance "d756" = 6; taper "d757" = 0 deg
sketch "Эскиз111"
  geometry: L1 (6.92, 133.315)-(6.92, 132.815); L2 (1.216, 128.497)-(1.216, 126.05); L3 (6.92, 131.315)-(6.92, 130.815); L4 (6.92, 129.315)-(6.92, 128.815); L5 (6.92, 127.315)-(6.92, 126.815); L6 (6.92, 125.315)-(6.92, 124.815); L7 (6.92, 123.315)-(6.92, 122.815); L8 (6.92, 121.315)-(6.92, 120.815); L9 (6.92, 119.315)-(6.92, 118.815); L10 (6.92, 117.315)-(6.92, 116.815); L11 (6.92, 115.315)-(6.92, 114.815); L12 (6.77, 134.665)-(7.4, 134.665); L13 (6.92, 113.315)-(6.92, 112.815); L14 (6.92, 111.315)-(6.92, 110.815); L15 (6.92, 109.315)-(6.92, 108.815); L16 (6.92, 107.315)-(6.92, 106.815); L17 (6.92, 105.315)-(6.92, 104.815); L18 (6.77, 105.465)-(7.4, 105.465); L19 (7.4, 105.465)-(7.4, 134.665); L20 (7.4, 0)-(7.4, 247) reference; L21 (7.4, 0)-(7.4, 247) reference; L22 (-7.4, 247)-(-7.4, 0) reference; L23 (6.55, 246.985)-(6, -0.013) reference; L24 (-6, -0.013)-(-6.55, 246.985) reference; A1 r 0.15 centre (6.77, 133.315) between (6.92, 133.315) and (6.77, 133.465); A2 r 0.15 centre (6.77, 132.815) between (6.77, 132.665) and (6.92, 132.815); A3 r 1 centre (6.77, 134.465) between (6.332, 133.566) and (6.77, 133.465); A4 r 0.555 centre (6.575, 134.065) between (6.332, 134.563) and (6.332, 133.566); A5 r 1 centre (6.77, 133.665) between (6.77, 134.665) and (6.332, 134.563); A6 r 0.15 centre (6.77, 131.315) between (6.92, 131.315) and (6.77, 131.465); A7 r 0.15 centre (6.77, 130.815) between (6.77, 130.665) and (6.92, 130.815); A8 r 1 centre (6.77, 132.465) between (6.332, 131.566) and (6.77, 131.465); A9 r 0.555 centre (6.575, 132.065) between (6.332, 132.563) and (6.332, 131.566); A10 r 1 centre (6.77, 131.665) between (6.77, 132.665) and (6.332, 132.563); A11 r 0.15 centre (6.77, 129.315) between (6.92, 129.315) and (6.77, 129.465); A12 r 0.15 centre (6.77, 128.815) between (6.77, 128.665) and (6.92, 128.815); A13 r 1 centre (6.77, 130.465) between (6.332, 129.566) and (6.77, 129.465); A14 r 0.555 centre (6.575, 130.065) between (6.332, 130.563) and (6.332, 129.566); A15 r 1 centre (6.77, 129.665) between (6.77, 130.665) and (6.332, 130.563); A16 r 0.15 centre (6.77, 127.315) between (6.92, 127.315) and (6.77, 127.465); A17 r 0.15 centre (6.77, 126.815) between (6.77, 126.665) and (6.92, 126.815); A18 r 1 centre (6.77, 128.465) between (6.332, 127.566) and (6.77, 127.465); A19 r 0.555 centre (6.575, 128.065) between (6.332, 128.563) and (6.332, 127.566); A20 r 1 centre (6.77, 127.665) between (6.77, 128.665) and (6.332, 128.563); A21 r 0.15 centre (6.77, 125.315) between (6.92, 125.315) and (6.77, 125.465); A22 r 0.15 centre (6.77, 124.815) between (6.77, 124.665) and (6.92, 124.815); A23 r 1 centre (6.77, 126.465) between (6.332, 125.566) and (6.77, 125.465); A24 r 0.555 centre (6.575, 126.065) between (6.332, 126.563) and (6.332, 125.566); A25 r 1 centre (6.77, 125.665) between (6.77, 126.665) and (6.332, 126.563); A26 r 0.15 centre (6.77, 123.315) between (6.92, 123.315) and (6.77, 123.465); A27 r 0.15 centre (6.77, 122.815) between (6.77, 122.665) and (6.92, 122.815); A28 r 1 centre (6.77, 124.465) between (6.332, 123.566) and (6.77, 123.465); A29 r 0.555 centre (6.575, 124.065) between (6.332, 124.563) and (6.332, 123.566); A30 r 1 centre (6.77, 123.665) between (6.77, 124.665) and (6.332, 124.563); A31 r 0.15 centre (6.77, 121.315) between (6.92, 121.315) and (6.77, 121.465); A32 r 0.15 centre (6.77, 120.815) between (6.77, 120.665) and (6.92, 120.815); A33 r 1 centre (6.77, 122.465) between (6.332, 121.566) and (6.77, 121.465); A34 r 0.555 centre (6.575, 122.065) between (6.332, 122.563) and (6.332, 121.566); A35 r 1 centre (6.77, 121.665) between (6.77, 122.665) and (6.332, 122.563); A36 r 0.15 centre (6.77, 119.315) between (6.92, 119.315) and (6.77, 119.465); A37 r 0.15 centre (6.77, 118.815) between (6.77, 118.665) and (6.92, 118.815); A38 r 1 centre (6.77, 120.465) between (6.332, 119.566) and (6.77, 119.465); A39 r 0.555 centre (6.575, 120.065) between (6.332, 120.563) and (6.332, 119.566); A40 r 1 centre (6.77, 119.665) between (6.77, 120.665) and (6.332, 120.563); A41 r 0.15 centre (6.77, 117.315) between (6.92, 117.315) and (6.77, 117.465); A42 r 0.15 centre (6.77, 116.815) between (6.77, 116.665) and (6.92, 116.815); A43 r 1 centre (6.77, 118.465) between (6.332, 117.566) and (6.77, 117.465); A44 r 0.555 centre (6.575, 118.065) between (6.332, 118.563) and (6.332, 117.566); A45 r 1 centre (6.77, 117.665) between (6.77, 118.665) and (6.332, 118.563); A46 r 0.15 centre (6.77, 115.315) between (6.92, 115.315) and (6.77, 115.465); A47 r 0.15 centre (6.77, 114.815) between (6.77, 114.665) and (6.92, 114.815); A48 r 1 centre (6.77, 116.465) between (6.332, 115.566) and (6.77, 115.465); A49 r 0.555 centre (6.575, 116.065) between (6.332, 116.563) and (6.332, 115.566); A50 r 1 centre (6.77, 115.665) between (6.77, 116.665) and (6.332, 116.563); A51 r 0.15 centre (6.77, 113.315) between (6.92, 113.315) and (6.77, 113.465); A52 r 0.15 centre (6.77, 112.815) between (6.77, 112.665) and (6.92, 112.815); A53 r 1 centre (6.77, 114.465) between (6.332, 113.566) and (6.77, 113.465); A54 r 0.555 centre (6.575, 114.065) between (6.332, 114.563) and (6.332, 113.566); A55 r 1 centre (6.77, 113.665) between (6.77, 114.665) and (6.332, 114.563); A56 r 0.15 centre (6.77, 111.315) between (6.92, 111.315) and (6.77, 111.465); A57 r 0.15 centre (6.77, 110.815) between (6.77, 110.665) and (6.92, 110.815); A58 r 1 centre (6.77, 112.465) between (6.332, 111.566) and (6.77, 111.465); A59 r 0.555 centre (6.575, 112.065) between (6.332, 112.563) and (6.332, 111.566); A60 r 1 centre (6.77, 111.665) between (6.77, 112.665) and (6.332, 112.563); A61 r 0.15 centre (6.77, 109.315) between (6.92, 109.315) and (6.77, 109.465); A62 r 0.15 centre (6.77, 108.815) between (6.77, 108.665) and (6.92, 108.815); A63 r 1 centre (6.77, 110.465) between (6.332, 109.566) and (6.77, 109.465); A64 r 0.555 centre (6.575, 110.065) between (6.332, 110.563) and (6.332, 109.566)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; 45 further points
  constraints: 150 point on circle, 75 centre point, 38 end point, 5 tangent, 5 vertical alignment, 4 vertical, 2 horizontal, 1 coincident, 1 equal radius, 1 parallel, 254 other
  dimensions: "d758" = 0.15 radius of A1; "d759" = 0.555 radius of A4; "d760" = 1 radius of A3; "d761" = 0.4 vertical distance of A5.centre A4.centre; "d764" = 2 distance of A1.end A6.end (derived); "d769" = 2 distance of A9.centre A4.centre; "d770" = 1.38 dimension on A74 L19
extrude "Выдавливание86" cut sketch "Эскиз111" distance "d771" = 6; taper "d772" = 0 deg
